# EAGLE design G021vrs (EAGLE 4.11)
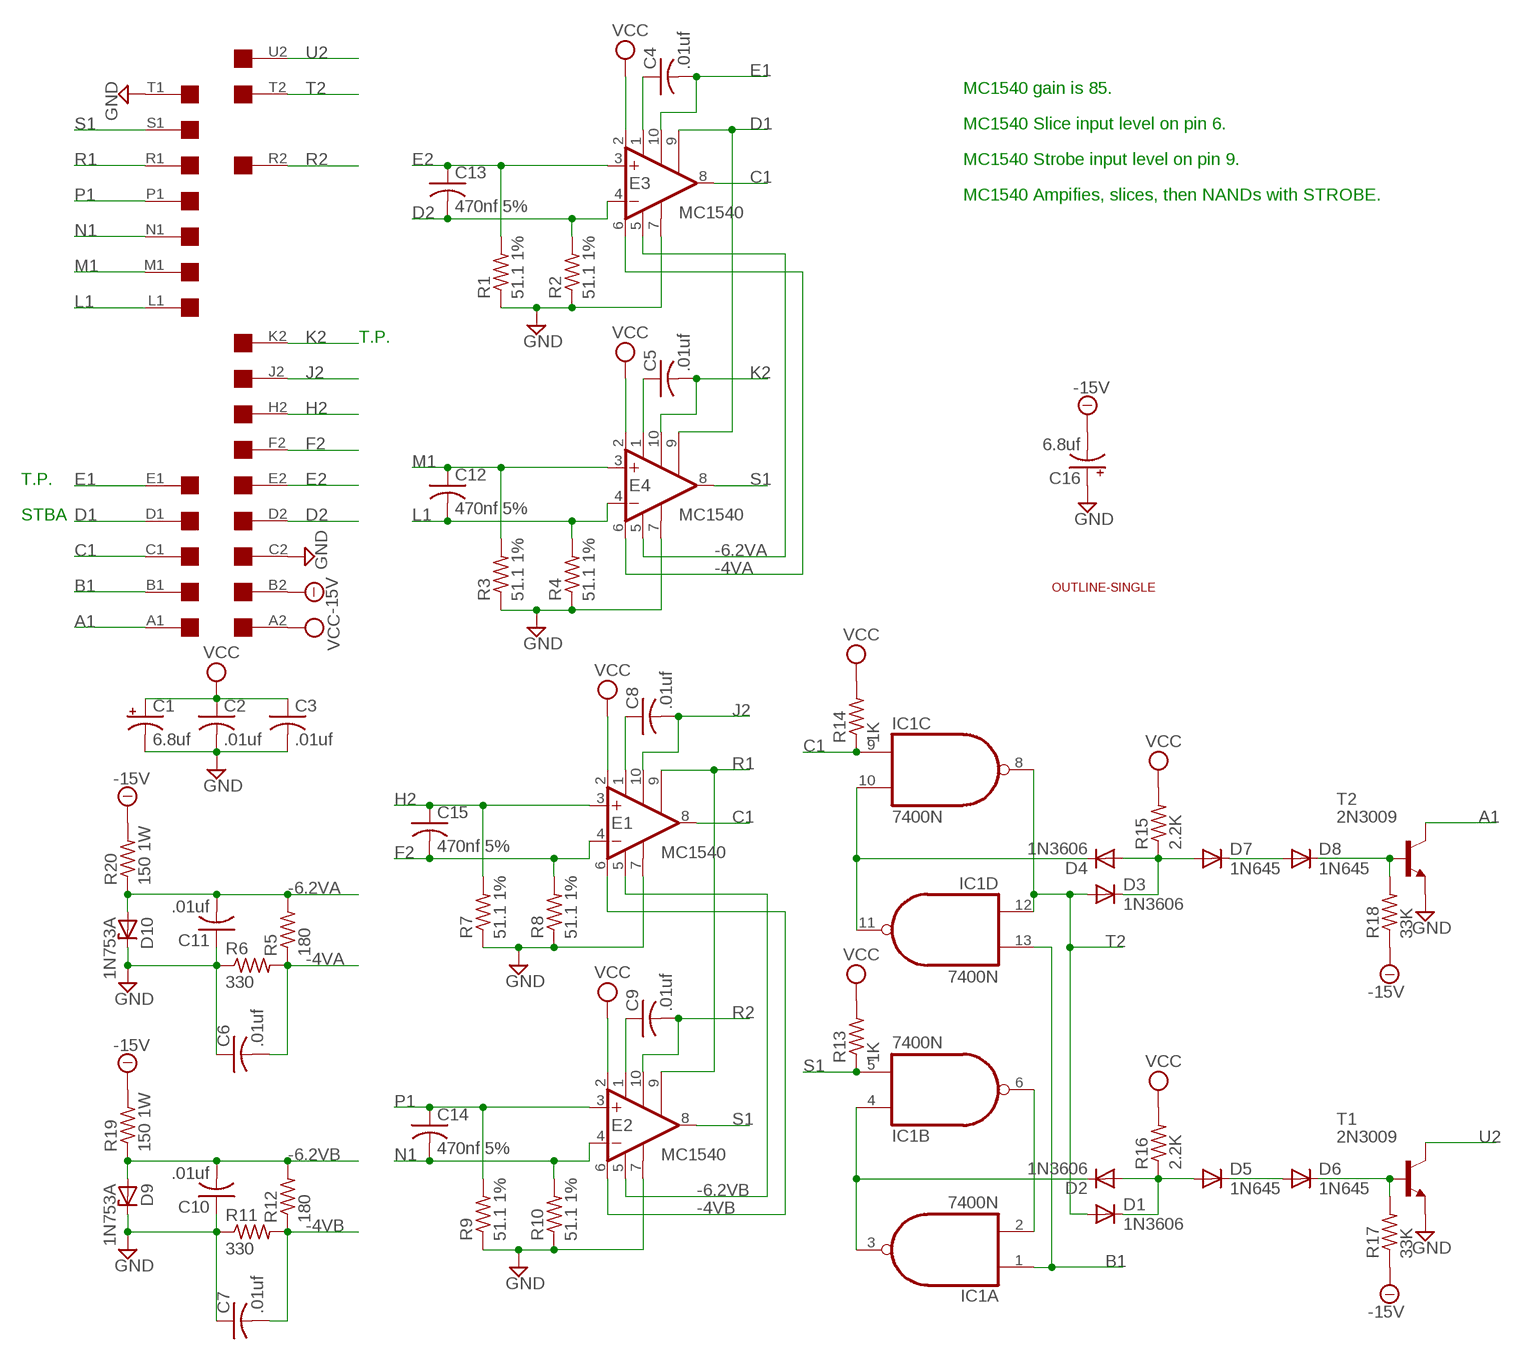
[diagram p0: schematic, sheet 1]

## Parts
C1  6.8uf  CPOL-USE15-5AXIAL  [E15-5]
C2  .01uf  C-US050-025X075  [C050-025X075]
C3  .01uf  C-US050-025X075  [C050-025X075]
C4  .01uf  C-US050-025X075  [C050-025X075]
C5  .01uf  C-US050-025X075  [C050-025X075]
C6  .01uf  C-US050-025X075  [C050-025X075]
C7  .01uf  C-US050-025X075  [C050-025X075]
C8  .01uf  C-US050-025X075  [C050-025X075]
C9  .01uf  C-US050-025X075  [C050-025X075]
C10  .01uf  C-US050-025X075  [C050-025X075]
C11  .01uf  C-US050-025X075  [C050-025X075]
C12  470nf 5%  C-US050-025X075  [C050-025X075]
C13  470nf 5%  C-US050-025X075  [C050-025X075]
C14  470nf 5%  C-US050-025X075  [C050-025X075]
C15  470nf 5%  C-US050-025X075  [C050-025X075]
C16  6.8uf  CPOL-USE15-5AXIAL  [E15-5]
D1  1N3606  1N4148  [DO35-10]
D2  1N3606  1N4148  [DO35-10]
D3  1N3606  1N4148  [DO35-10]
D4  1N3606  1N4148  [DO35-10]
D5  1N645  1N4148  [DO35-10]
D6  1N645  1N4148  [DO35-10]
D7  1N645  1N4148  [DO35-10]
D8  1N645  1N4148  [DO35-10]
D9  1N753A  ZENER-DIODEF126-10  [F126Z10]
D10  1N753A  ZENER-DIODEF126-10  [F126Z10]
E1  MC1540  [TO100]
E2  MC1540  [TO100]
E3  MC1540  [TO100]
E4  MC1540  [TO100]
IC1  7400N  [DIL14]
R1  51.1 1%  R-US_0207/10  [0207/10]
R2  51.1 1%  R-US_0207/10  [0207/10]
R3  51.1 1%  R-US_0207/10  [0207/10]
R4  51.1 1%  R-US_0207/10  [0207/10]
R5  180  R-US_0207/10  [0207/10]
R6  330  R-US_0207/10  [0207/10]
R7  51.1 1%  R-US_0207/10  [0207/10]
R8  51.1 1%  R-US_0207/10  [0207/10]
R9  51.1 1%  R-US_0207/10  [0207/10]
R10  51.1 1%  R-US_0207/10  [0207/10]
R11  330  R-US_0207/10  [0207/10]
R12  180  R-US_0207/10  [0207/10]
R13  1K  R-US_0207/10  [0207/10]
R14  1K  R-US_0207/10  [0207/10]
R15  2.2K  R-US_0207/10  [0207/10]
R16  2.2K  R-US_0207/10  [0207/10]
R17  33K  R-US_0207/10  [0207/10]
R18  33K  R-US_0207/10  [0207/10]
R19  150 1W  R-US_0414/15  [0414/15]
R20  150 1W  R-US_0414/15  [0414/15]
T1  2N3009  2N3565  [TO92]
T2  2N3009  2N3565  [TO92]
U$1  SINGLE  [EDGE-CON2]
U$2  OUTLINE-SINGLE  [SINGLE]

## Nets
-4VA: C6.2 E3.6(SLICE) E4.6(SLICE) R5.1 R6.2
-4VB: C7.2 E1.6(SLICE) E2.6(SLICE) R11.2 R12.1
-6.2VA: C11.2 D10.A E3.5(V-) E4.5(V-) R5.2 R20.1
-6.2VB: C10.2 D9.A E1.5(V-) E2.5(V-) R12.2 R19.1
-15V: C16.- R17.1 R18.1 R19.2 R20.2 U$1.B2
A1: T2.1(C) U$1.A1
B1: IC1.1(A:I0) IC1.13(D:I1) U$1.B1
C1: E1.8(OUT) E3.8(OUT) IC1.9(C:I0) R14.1 U$1.C1
D1: E3.9(ISTROBE) E4.9(ISTROBE) U$1.D1
D2: C13.2 E3.4(-IN) R2.2 U$1.D2
E1: C4.2 E3.10(CEXTB) U$1.E1
E2: C13.1 E3.3(+IN) R1.2 U$1.E2
F2: C15.2 E1.4(-IN) R8.2 U$1.F2
GND [supply]: C1.- C2.2 C3.2 C6.1 C7.1 C10.1 C11.1 C16.+ D9.C D10.C E1.7(GND) E2.7(GND) E3.7(GND) E4.7(GND) R1.1 R2.1 R3.1 R4.1 R6.1 R7.1 R8.1 R9.1 R10.1 R11.1 T1.3(E) T2.3(E) U$1.C2 U$1.T1
H2: C15.1 E1.3(+IN) R7.2 U$1.H2
J2: C8.2 E1.10(CEXTB) U$1.J2
K2: C5.2 E4.10(CEXTB) U$1.K2
L1: C12.2 E4.4(-IN) R4.2 U$1.L1
M1: C12.1 E4.3(+IN) R3.2 U$1.M1
N1: C14.2 E2.4(-IN) R10.2 U$1.N1
N$1: C4.1 E3.1(CEXTA)
N$2: C8.1 E1.1(CEXTA)
N$3: C5.1 E4.1(CEXTA)
N$4: C9.1 E2.1(CEXTA)
N$6: D1.C D2.A D5.A R16.1
N$7: D4.C IC1.10(C:I1) IC1.11(D:O)
N$8: D2.C IC1.3(A:O) IC1.4(B:I0)
N$9: IC1.2(A:I1) IC1.6(B:O)
N$10: D3.C D4.A D7.A R15.1
N$11: D7.C D8.A
N$12: D5.C D6.A
N$13: D8.C R18.2 T2.2(B)
N$14: D6.C R17.2 T1.2(B)
P1: C14.1 E2.3(+IN) R9.2 U$1.P1
R1: E1.9(ISTROBE) E2.9(ISTROBE) U$1.R1
R2: C9.2 E2.10(CEXTB) U$1.R2
S1: E2.8(OUT) E4.8(OUT) IC1.5(B:I1) R13.1 U$1.S1
T2: D1.A D3.A IC1.8(C:O) IC1.12(D:I0) U$1.T2
U2: T1.1(C) U$1.U2
VCC [supply]: C1.+ C2.1 C3.1 E1.2(V+) E2.2(V+) E3.2(V+) E4.2(V+) R13.2 R14.2 R15.2 R16.2 U$1.A2
Unconnected: U$1.F1 U$1.H1 U$1.J1 U$1.K1 U$1.L2 U$1.M2 U$1.N2 U$1.P2 U$1.S2 U$1.U1 U$1.V1 U$1.V2

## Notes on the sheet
- MC1540 gain is 85.
- MC1540 Slice input level on pin 6.
- MC1540 Strobe input level on pin 9.
- MC1540 Ampifies, slices, then NANDs with STROBE.
- T.P.
- T.P.
- STBA

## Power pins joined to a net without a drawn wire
GND: IC1.7(P:GND)
VCC: IC1.14(P:VCC)

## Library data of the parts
C1 C16 = rcl:CPOL-US: POLARIZED CAPACITOR, American symbol
C2-C15 = rcl:C-US: CAPACITOR, American symbol
D1-D8 = diode:1N4148: DIODE
D9 D10 = diode:ZENER-DIODE: Z-Diode
E1-E4 = dec-con:MC1540: OP AMP
IC1 = 74xx-us:74*00: Quad 2-input NAND gate
R1-R20 = rcl:R-US_: RESISTOR, American symbol
T1 T2 = transistor:2N3565: NPN TRANSISTOR
U$1 = dec-con:SINGLE: Double-Height DEC board
U$2 = dec-con:OUTLINE-*: Board outlines for DEC boards.

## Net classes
1 supply: width 0.762 mm, drill 0.635 mm

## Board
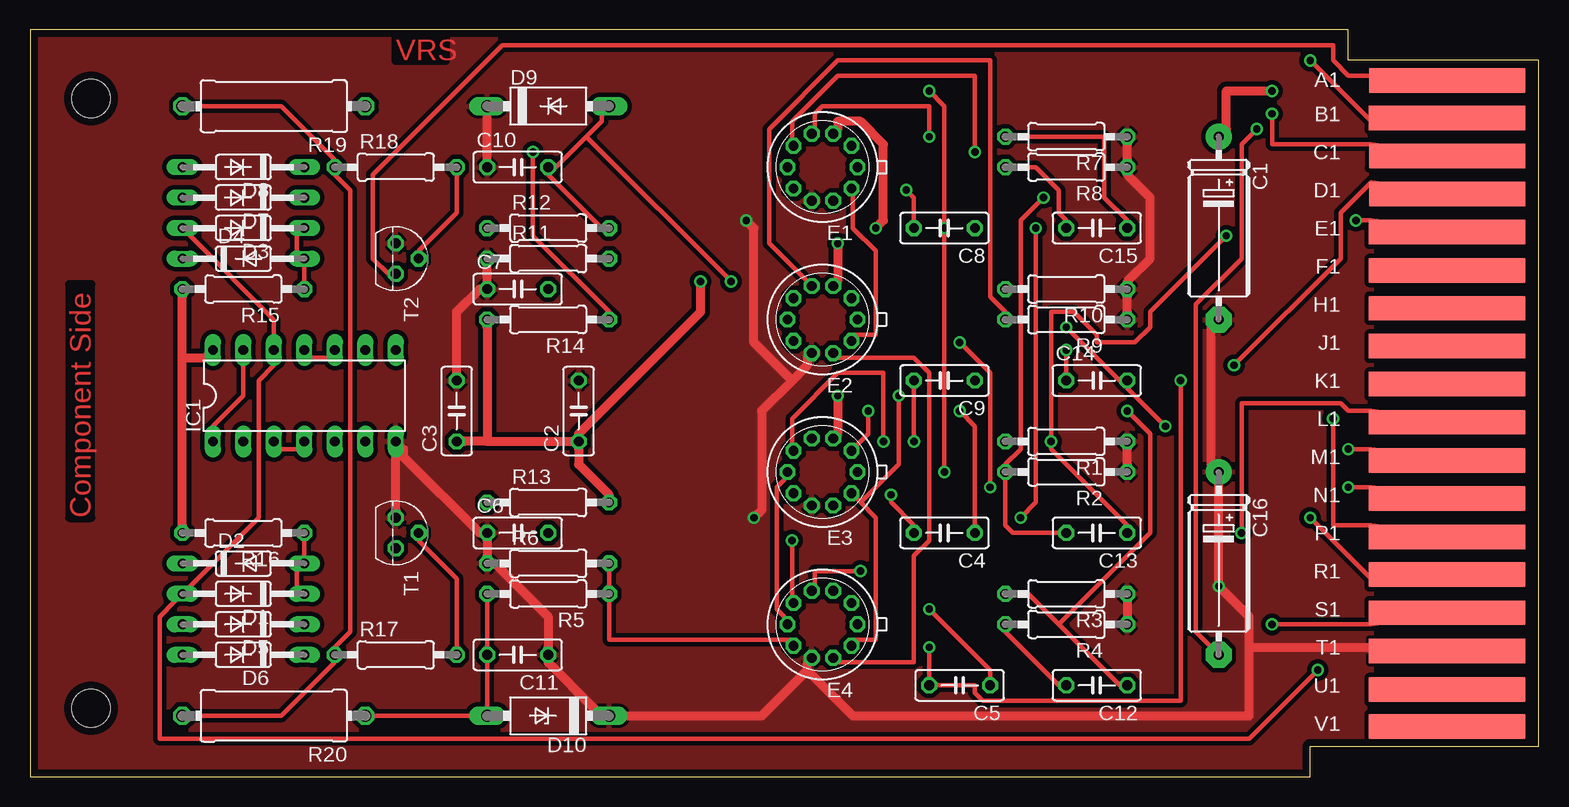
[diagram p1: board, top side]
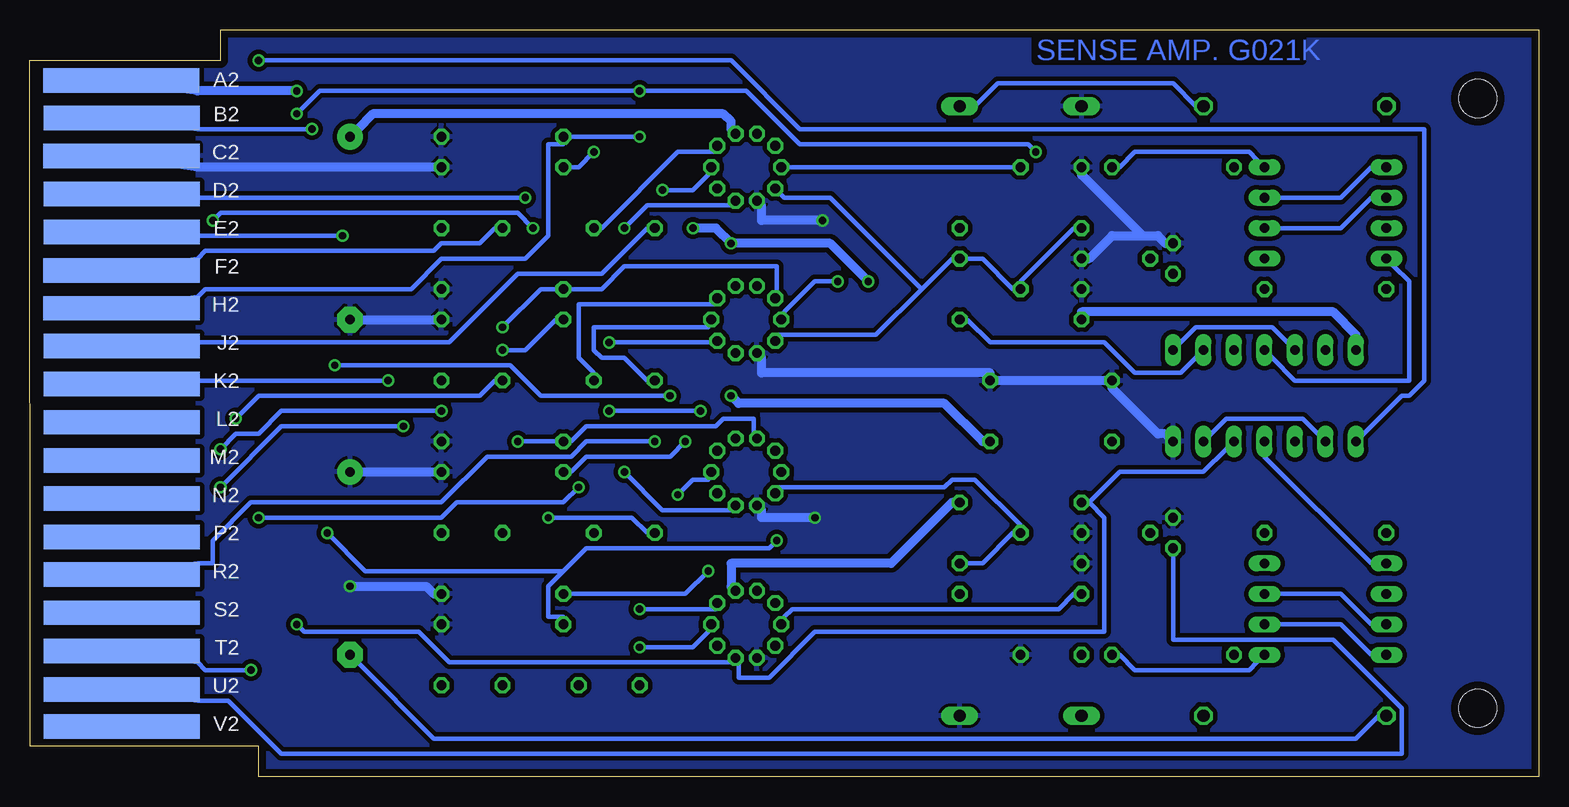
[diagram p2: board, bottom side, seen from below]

Size 125.73 x 62.23 mm. Coordinates in mm from the lower left corner, seen from the top.
Copper layers (1*16): Top 0.035mm / dielectric 1.5mm / Bottom 0.035mm
Design rules "15mils": minimum track width 15mil, minimum drill 24mil, track to track 15mil, track to pad 10mil, pad to pad 10mil, via to via 10mil, smd to smd 10mil, copper to edge 25mil, drill to drill 10mil, minimum pad ring 10mil, minimum via ring 8mil, stop-mask expansion 0mil, vias tented up to drill 0mil, thermal gap 10mil

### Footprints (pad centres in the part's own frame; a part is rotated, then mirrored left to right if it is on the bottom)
E15-5 = drill 0.813 pad 2.159 round: + -7.62,0 | drill 0.813 pad 2.159 octagon: - 7.62,0
C050-025X075 = drill 0.813 octagon: 1 -2.54,0; 2 2.54,0
DO35-10 = drill 0.813 long: A 5.08,0; C -5.08,0
F126Z10 = drill 1.016 long: A 5.08,0; C -5.08,0
TO100 = drill 0.813 octagon: 1 -2.413,-1.778; 2 -0.889,-2.794; 3 0.889,-2.794; 4 2.413,-1.778; 5 2.921,0; 6 2.413,1.778; 7 0.889,2.794; 8 -0.889,2.794; 9 -2.413,1.778; 10 -2.921,0
DIL14 = drill 0.813 long: 1 -7.62,-3.81; 2 -5.08,-3.81; 3 -2.54,-3.81; 4 0,-3.81; 5 2.54,-3.81; 6 5.08,-3.81; 7 7.62,-3.81; 8 7.62,3.81; 9 5.08,3.81; 10 2.54,3.81; 11 0,3.81; 12 -2.54,3.81; 13 -5.08,3.81; 14 -7.62,3.81
0207/10 = drill 0.813 octagon: 1 -5.08,0; 2 5.08,0
0414/15 = drill 1.016 octagon: 1 -7.62,0; 2 7.62,0
TO92 = drill 0.813 octagon: 1 1.27,0; 2 0,1.905; 3 -1.27,0
EDGE-CON2 = smd 13.017 x 2.032: A1 7.633,4.207; B1 7.639,7.327; C1 7.636,10.489; D1 7.633,13.665; E1 7.642,16.84; F1 7.642,20.041; H1 7.642,23.19; J1 7.642,26.34; K1 7.642,29.515; L1 7.642,32.69; M1 7.642,35.89; N1 7.642,39.04; P1 7.642,42.24; R1 7.642,45.39; S1 7.642,48.565; T1 7.642,51.74; U1 7.642,54.966; V1 7.642,58.026 | smd 13.017 x 2.032 bottom: A2 7.614,4.207; B2 7.642,7.328; C2 7.617,10.49; D2 7.642,13.665; E2 7.642,16.84; F2 7.617,20.041; H2 7.617,23.19; J2 7.642,26.34; K2 7.642,29.515; L2 7.642,32.69; M2 7.642,35.89; N2 7.642,39.04; P2 7.642,42.24; R2 7.642,45.39; S2 7.642,48.565; T2 7.642,51.74; U2 7.642,54.966; V2 7.642,58.026
SINGLE = hole 3.175: 120.65,56.515; 120.65,5.715

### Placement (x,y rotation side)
C1  99.06,45.72 270 top
C2  45.72,30.48 90 top
C3  35.56,30.48 90 top
C4  76.2,20.32 180 top
C5  77.47,7.62 180 top
C6  40.64,20.32 0 top
C7  40.64,40.64 0 top
C8  76.2,45.72 180 top
C9  76.2,33.02 180 top
C10  40.64,50.8 0 top
C11  40.64,10.16 180 top
C12  88.9,7.62 180 top
C13  88.9,20.32 180 top
C14  88.9,33.02 0 top
C15  88.9,45.72 180 top
C16  99.06,17.78 270 top
D1  17.78,15.24 180 top
D2  17.78,17.78 0 top
D3  17.78,45.72 180 top
D4  17.78,43.18 0 top
D5  17.78,12.7 180 top
D6  17.78,10.16 180 top
D7  17.78,48.26 180 top
D8  17.78,50.8 180 top
D9  43.18,55.88 0 top
D10  43.18,5.08 180 top
E1  66.04,50.8 180 top
E2  66.04,38.1 180 top
E3  66.04,25.4 180 top
E4  66.04,12.7 180 top
IC1  22.86,31.75 0 top
R1  86.36,27.94 180 top
R2  86.36,25.4 180 top
R3  86.36,15.24 180 top
R4  86.36,12.7 180 top
R5  43.18,15.24 180 top
R6  43.18,17.78 0 top
R7  86.36,53.34 180 top
R8  86.36,50.8 180 top
R9  86.36,38.1 180 top
R10  86.36,40.64 180 top
R11  43.18,43.18 0 top
R12  43.18,45.72 0 top
R13  43.18,22.86 0 top
R14  43.18,38.1 180 top
R15  17.78,40.64 180 top
R16  17.78,20.32 180 top
R17  30.48,10.16 0 top
R18  30.48,50.8 0 top
R19  20.32,55.88 180 top
R20  20.32,5.08 180 top
T1  30.48,20.32 270 top
T2  30.48,43.18 270 top
U$1  125.73,62.23 180 top
U$2  125.73,62.23 180 top

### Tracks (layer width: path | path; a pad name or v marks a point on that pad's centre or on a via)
-4VA
  Top 0.381: R6.2 48.26,17.14 48.26,15.88 R5.1 48.26,14.61 48.26,11.43 63.5,11.43 E4.6
  Bottom 0.381: R6.2 47.62,17.78 46.35,17.78 43.81,20.32 C6.2 43.18,20.95 46.99,24.77 48.9,24.77 49.53,24.13 63.5,24.13 E3.6
-4VB
  Bottom 0.381: R12.1 38.73,45.72 43.18,41.27 C7.2 43.81,40.64 46.35,43.18 47.62,43.18 R11.2 48.9,43.18 51.44,40.64 | 51.44,40.64 55.24,36.83 63.5,36.83 E2.6 | 51.44,40.64 59.05,48.26 62.87,48.26 63.5,48.9 E1.6
-6.2VA
  Top 0.381: E4.5 62.87,13.34 62.23,13.97 62.23,24.13 62.87,24.77 E3.5 | R5.2 38.1,14.61 38.1,10.79 C11.2 38.1,9.53 38.1,5.71 D10.A 36.83,5.08 28.57,5.08 R20.1
  Bottom 0.381: E4.5 62.87,13.34 62.23,13.97 40.01,13.97 38.73,15.24 R5.2
-6.2VB  (via drill 0.61)
  Top 0.381: 46.35,53.34 47.62,54.61 47.62,55.24 D9.A | 46.35,53.34 43.81,50.8 C10.2 43.18,50.16 47.62,45.72 R12.2 | 46.35,53.34 v58.42,41.27
  Bottom 0.381: v58.42,41.27 60.33,41.27 62.87,38.73 E2.5 | E1.5 62.87,50.8 43.81,50.8 C10.2 | R19.1 28.57,55.88 30.48,57.78 45.09,57.78 46.99,55.88 D9.A
-15V  (via drill 0.61)
  Top 0.381: R19.2 13.34,55.88 20.95,55.88 25.4,51.44 R18.1 25.4,50.16 26.67,48.9 26.67,12.06 25.4,10.79 R17.1 25.4,9.53 20.95,5.08 13.34,5.08 R20.2 | v102.23,53.98 100.97,52.7 100.97,43.18 97.16,39.37 97.16,12.06 98.42,10.79 C16.-
  Bottom 0.381: C16.- 98.42,9.53 92.08,3.17 15.24,3.17 13.34,5.08 R20.2 | v102.23,53.98 111.76,53.98 U$1.B2
A1
  Top 0.381: T2.1 29.84,41.91 28.57,43.18 28.57,50.16 39.37,60.96 108.58,60.96 108.58,59.69 109.86,58.42 111.76,58.42 U$1.A1
B1  (via drill 0.61)
  Top 0.381: IC1.1 15.24,29.21 17.78,31.75 17.78,34.29 IC1.13 | v106.68,59.69 111.76,54.61 U$1.B1
  Bottom 0.381: v106.68,59.69 67.31,59.69 61.59,53.98 9.53,53.98 9.53,33.02 10.79,31.75 11.43,31.75 14.61,28.57 IC1.1
C1  (via drill 0.61)
  Top 0.381: v76.2,25.4 v76.2,45.72 76.2,55.88 v74.93,57.15 | v41.91,52.07 41.91,45.09 48.26,38.73 R14.1 | v103.5,55.24 103.5,52.7 111.76,52.7 U$1.C1
  Bottom 0.381: IC1.9 28.57,34.92 29.84,33.66 33.66,33.66 36.2,36.2 45.72,36.2 47.62,38.1 R14.1 | v76.2,25.4 73.03,22.23 67.31,22.23 E3.8 | v76.2,45.72 74.3,47.62 67.31,47.62 E1.8 | v41.91,52.07 42.55,52.7 61.59,52.7 66.04,57.15 v74.93,57.15 101.6,57.15 v103.5,55.24
D1  (via drill 0.61)
  Top 0.381: 69.22,22.86 68.58,23.5 E3.9 | 69.22,22.86 70.48,21.59 70.48,11.43 68.58,11.43 E4.9 | 69.22,22.86 72.39,26.04 v72.39,31.75 | v100.33,34.29 109.22,43.18 109.22,46.99 111.76,49.53 U$1.D1
  Bottom 0.381: v72.39,31.75 83.19,31.75 85.72,34.29 v100.33,34.29
D2  (via drill 0.61)
  Top 0.381: C13.2 85.72,20.32 81.92,20.32 81.28,20.95 81.28,24.77 R2.2 81.28,26.04 82.55,27.3 82.55,46.35 v84.45,48.26 | v71.12,27.94 71.12,33.66 67.31,33.66 63.5,29.84 63.5,27.3 E3.4
  Bottom 0.381: v71.12,27.94 72.39,26.67 79.38,26.67 80.64,25.4 R2.2 | v84.45,48.26 111.76,48.26 U$1.D2
E1  (via drill 0.61)
  Top 0.381: v71.75,23.5 71.75,22.86 73.66,20.95 C4.2 | v82.55,21.59 83.82,22.86 v83.82,45.72 | v110.49,46.35 111.76,46.35 U$1.E1
  Bottom 0.381: v71.75,23.5 70.48,24.77 69.22,24.77 E3.10 | v82.55,21.59 75.56,21.59 74.3,20.32 C4.2 | v83.82,45.72 85.09,46.99 109.86,46.99 v110.49,46.35
E2  (via drill 0.61)
  Top 0.381: C13.1 91.44,20.95 85.09,27.3 v85.09,27.94 85.09,38.73 87,38.73 88.9,36.83 88.9,36.2 92.08,36.2 93.34,37.47 93.34,38.73 v99.69,45.09
  Bottom 0.381: E3.3 65.41,28.57 65.41,29.84 67.94,29.84 68.58,29.21 79.38,29.21 80.64,27.94 R1.2 81.92,27.94 v85.09,27.94 | v99.69,45.09 111.76,45.09 U$1.E2
F2  (via drill 0.61)
  Top 0.381: C15.2 86.36,46.35 85.72,46.99 85.72,48.9 83.82,50.8 81.92,50.8 R8.2 | v78.74,52.07 78.74,58.42 67.31,58.42 63.5,54.61 63.5,52.7 E1.4
  Bottom 0.381: v78.74,52.07 80.01,50.8 80.64,50.8 R8.2 | U$1.F2 111.76,43.18 111.12,43.81 92.08,43.81 91.44,44.45 88.27,44.45 87,45.72 C15.2
GND  (via drill 0.61)
  Top 0.762: 64.77,8.89 64.77,9.53 E4.7 | 64.77,8.89 60.96,5.08 49.53,5.08 D10.C 46.99,5.08 46.99,5.71 43.18,9.53 C11.1 43.18,10.79 43.18,13.34 38.73,17.78 R6.1 38.1,18.41 38.1,19.68 C6.1 37.47,20.32 31.11,26.67 31.11,27.3 IC1.7 30.48,26.67 30.48,22.23 T1.3 | v60.33,21.59 60.96,22.23 60.96,30.48 63.5,33.02 | 63.5,33.02 64.77,34.29 64.77,34.92 E2.7 | v59.69,46.35 60.33,45.72 60.33,36.2 63.5,33.02 | C10.1 38.1,51.44 38.1,55.24 D9.C | R11.1 38.1,42.55 38.1,41.27 C7.1 37.47,40.64 35.56,38.73 35.56,33.66 C3.2 | R2.1 91.44,26.04 91.44,27.3 R1.1 | R4.1 91.44,13.34 91.44,14.61 R3.1 | R7.1 91.44,52.7 91.44,51.44 R8.1 91.44,50.16 93.34,48.26 93.34,43.18 91.44,41.27 R10.1 91.44,40.01 91.44,38.73 R9.1 | C1.- 98.42,37.47 98.42,26.04 C16.+ 99.06,24.77 v99.06,15.88 101.6,13.34 101.6,10.79 | 101.6,10.79 111.76,10.79 U$1.T1 | 64.77,8.89 68.58,5.08 101.6,5.08 101.6,10.79
  Bottom 0.762: v60.33,21.59 64.77,21.59 64.77,22.23 E3.7 | v59.69,46.35 64.77,46.35 64.77,47.62 E1.7 | 33.02,45.09 35.56,45.09 37.47,43.18 R11.1 | 33.02,45.09 31.75,45.09 31.11,44.45 T2.3 | 33.02,45.09 38.1,50.16 C10.1 | IC1.7 31.11,28.57 31.75,28.57 35.56,32.38 C3.2 36.2,33.02 45.09,33.02 C2.2 45.72,33.66 64.77,33.66 64.77,34.92 E2.7 | v99.06,15.88 92.71,15.88 92.08,15.24 R3.1 | R2.1 92.08,25.4 98.42,25.4 C16.+ | R9.1 92.08,38.1 98.42,38.1 C1.- | U$1.C2 111.76,50.8 92.08,50.8 R8.1
  pour Bottom: 0,62.23 111.76,62.23 111.76,0 0,0
  pour Top: 0,62.23 111.76,62.23 111.76,0 0,0
H2  (via drill 0.61)
  Top 0.381: R7.2 81.92,53.34 89.53,53.34 89.53,48.26 91.44,46.35 C15.1 | v74.93,53.34 74.93,55.88 66.04,55.88 65.41,55.24 65.41,53.98 E1.3
  Bottom 0.381: v74.93,53.34 80.64,53.34 R7.2 81.28,52.7 82.55,52.7 82.55,45.09 84.45,43.18 91.44,43.18 93.98,40.64 111.12,40.64 111.76,40.01 U$1.H2
J2  (via drill 0.61)
  Top 0.381: v73.03,48.9 73.66,48.26 73.66,46.35 C8.2
  Bottom 0.381: C8.2 74.3,45.72 78.11,41.91 85.09,41.91 90.81,36.2 111.76,36.2 U$1.J2 | v73.03,48.9 70.48,48.9 69.22,50.16 E1.10
K2  (via drill 0.61)
  Top 0.381: v74.93,10.79 74.93,8.26 C5.2 75.56,7.62 78.74,7.62 78.74,6.99 79.38,6.35 95.89,6.35 v95.89,33.02
  Bottom 0.381: v74.93,10.79 70.48,10.79 69.22,12.06 E4.10 | v95.89,33.02 111.76,33.02 U$1.K2
L1  (via drill 0.61)
  Top 0.381: R4.2 81.28,12.06 85.72,7.62 C12.2 | v63.5,19.68 63.5,14.61 E4.4 | v100.97,20.32 100.97,31.11 109.22,31.11 109.86,30.48 111.76,30.48 U$1.L1
  Bottom 0.381: v63.5,19.68 64.14,19.05 79.38,19.05 81.28,17.14 | 81.28,17.14 82.55,15.88 82.55,13.34 81.28,13.34 R4.2 | v100.97,20.32 97.79,17.14 81.28,17.14
M1  (via drill 0.61)
  Top 0.381: 85.72,12.7 83.19,15.24 81.92,15.24 R3.2 | 85.72,12.7 90.81,7.62 C12.1 | v69.22,17.14 65.41,17.14 65.41,15.88 E4.3 | v109.86,27.3 111.76,27.3 U$1.M1 | v91.44,30.48 93.34,28.57 93.34,20.32 85.72,12.7
  Bottom 0.381: v69.22,17.14 71.12,15.24 80.64,15.24 R3.2 | v109.86,27.3 108.58,28.57 106.68,28.57 104.78,30.48 v91.44,30.48
N1  (via drill 0.61)
  Top 0.381: v86.36,37.47 90.81,33.02 C14.2 91.44,32.38 v94.61,29.21 | v109.86,24.13 111.76,24.13 U$1.N1
  Bottom 0.381: E2.4 63.5,40.01 63.5,42.55 76.2,42.55 78.11,40.64 80.64,40.64 R10.2 81.92,40.64 83.19,40.64 v86.36,37.47 | v109.86,24.13 104.78,29.21 v94.61,29.21
N$1  (via drill 0.61)
  Top 0.381: v69.85,30.48 69.85,28.57 68.58,27.3 E3.1 | v77.47,30.48 78.74,29.21 78.74,20.95 C4.1
  Bottom 0.381: v69.85,30.48 v77.47,30.48
N$2
  Bottom 0.381: C8.1 78.11,45.72 71.75,52.07 68.58,52.07 E1.1
N$3  (via drill 0.61)
  Top 0.381: v74.93,13.97 80.01,8.89 80.01,8.26 C5.1
  Bottom 0.381: v74.93,13.97 68.58,13.97 E4.1
N$4
  Bottom 0.381: C9.1 78.74,33.66 80.01,34.92 80.01,39.37 68.58,39.37 E2.1
N$6
  Top 0.381: D1.C 22.23,15.88 22.23,17.14 D2.A 22.86,18.41 22.86,19.68 R16.1
  Bottom 0.381: D5.A 13.97,12.7 16.51,15.24 21.59,15.24 D1.C
N$7
  Top 0.381: IC1.11 23.5,34.92 24.77,34.92 IC1.10
  Bottom 0.381: D4.C 12.06,42.55 10.79,41.27 10.79,33.02 20.32,33.02 22.23,34.92 IC1.11
N$8
  Top 0.381: IC1.3 20.95,27.3 22.23,27.3 IC1.4
  Bottom 0.381: D2.C 13.97,17.78 22.86,26.67 IC1.4
N$9
  Bottom 0.381: IC1.2 18.41,28.57 19.68,29.84 26.04,29.84 27.3,28.57 IC1.6
N$10
  Top 0.381: R15.1 22.86,41.27 22.86,42.55 D4.A 22.23,43.81 22.23,45.09 D3.C
  Bottom 0.381: D7.A 13.97,48.26 16.51,45.72 21.59,45.72 D3.C
N$11
  Bottom 0.381: D8.A 13.97,50.8 16.51,48.26 21.59,48.26 D7.C
N$12
  Bottom 0.381: D6.A 13.97,10.16 16.51,12.7 21.59,12.7 D5.C
N$13
  Top 0.381: T2.2 32.38,43.81 35.56,46.99 35.56,50.16 R18.2
  Bottom 0.381: D8.C 23.5,51.44 24.13,52.07 33.66,52.07 34.92,50.8 R18.2
N$14
  Top 0.381: T1.2 32.38,19.68 35.56,16.51 35.56,10.79 R17.2
  Bottom 0.381: D6.C 23.5,9.53 24.13,8.89 33.66,8.89 34.92,10.16 R17.2
P1  (via drill 0.61)
  Top 0.381: v86.36,35.56 86.36,33.66 C14.1 | E2.3 64.77,41.27 61.59,44.45 61.59,53.98 67.31,59.69 80.01,59.69 80.01,40.01 81.28,38.73 R9.2 | v108.58,29.84 108.58,20.95 111.76,20.95 U$1.P1
  Bottom 0.381: v86.36,35.56 84.45,35.56 81.92,38.1 R9.2 | v108.58,29.84 106.68,31.75 88.27,31.75 87,33.02 C14.1
R1  (via drill 0.61)
  Top 0.381: E2.9 68.58,36.83 70.48,36.83 70.48,43.81 68.58,45.72 68.58,48.9 E1.9 | v77.47,36.2 80.01,33.66 v80.01,24.13 | v106.68,21.59 111.76,16.51 U$1.R1
  Bottom 0.381: v77.47,36.2 68.58,36.2 E2.9 | v80.01,24.13 81.28,22.86 90.17,22.86 91.44,21.59 v106.68,21.59
R2  (via drill 0.61)
  Top 0.381: v73.66,27.94 73.66,32.38 C9.2
  Bottom 0.381: C9.2 74.3,33.02 76.2,34.92 78.11,34.92 78.74,35.56 78.74,37.47 69.22,37.47 E2.10 | v73.66,27.94 79.38,27.94 80.64,26.67 87.63,26.67 91.44,22.86 107.31,22.86 110.49,19.68 110.49,17.78 111.76,17.78 U$1.R2
S1  (via drill 0.61)
  Top 0.381: E4.8 67.31,9.53 73.66,9.53 73.66,18.41 74.93,19.68 74.93,33.66 73.66,34.92 67.31,34.92 E2.8 | v103.5,12.7 111.76,12.7 U$1.S1
  Bottom 0.381: 37.47,22.86 34.92,25.4 27.94,25.4 26.04,27.3 IC1.5 | 37.47,22.86 R13.1 37.47,22.86 | 37.47,22.86 36.2,21.59 36.2,12.06 60.33,12.06 64.14,8.26 66.67,8.26 66.67,9.53 E4.8 67.31,9.53 90.81,9.53 93.34,12.06 102.87,12.06 v103.5,12.7
T2  (via drill 0.61)
  Top 0.381: D3.A 13.34,45.09 20.32,38.1 20.32,36.83 IC1.12 20.32,34.29 19.05,33.02 19.05,21.59 13.34,15.88 D1.A 12.06,14.61 10.79,13.34 10.79,3.17 101.6,3.17 v107.31,8.89
  Bottom 0.381: IC1.8 29.84,36.2 28.57,37.47 22.23,37.47 20.95,36.2 IC1.12 | v107.31,8.89 111.12,8.89 111.76,9.53 U$1.T2
U2
  Bottom 0.381: T1.1 30.48,18.41 30.48,11.43 17.14,11.43 11.43,5.71 11.43,1.91 104.78,1.91 109.22,6.35 111.76,6.35 U$1.U2
VCC  (via drill 0.61)
  Top 0.762: 12.7,34.92 12.7,40.01 R15.2 | 12.7,34.92 12.7,20.95 R16.2 | 12.7,34.92 14.61,34.92 IC1.14 | 38.1,27.94 45.09,27.94 C2.1 | 38.1,27.94 36.2,27.94 C3.1 | R13.2 48.26,23.5 45.72,26.04 45.72,27.3 C2.1 | 38.1,27.94 38.1,37.47 R14.2 | v67.31,31.75 67.31,28.57 E3.2 | v67.31,44.45 67.31,41.27 E2.2 | v70.48,45.72 71.12,46.35 71.12,52.7 69.22,54.61 67.31,54.61 67.31,53.98 E1.2 | v103.5,57.15 99.69,57.15 99.69,53.98 C1.+ | v55.88,41.27 55.88,38.73 45.72,28.57 C2.1
  Bottom 0.762: E4.2 67.31,15.88 67.31,17.78 53.98,17.78 48.9,22.86 R13.2 | v67.31,31.75 66.67,31.11 49.53,31.11 46.35,27.94 C2.1 | IC1.14 15.24,36.83 17.14,38.73 38.1,38.73 R14.2 | v70.48,45.72 68.58,45.72 v67.31,44.45 59.05,44.45 v55.88,41.27 | C1.+ 98.42,53.98 97.16,55.24 67.94,55.24 67.31,54.61 67.31,53.98 E1.2 | v103.5,57.15 111.76,57.15 U$1.A2

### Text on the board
Top: VRS | Component Side
Bottom: SENSE AMP. G021K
